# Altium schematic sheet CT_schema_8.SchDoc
size 274 x 160 mm
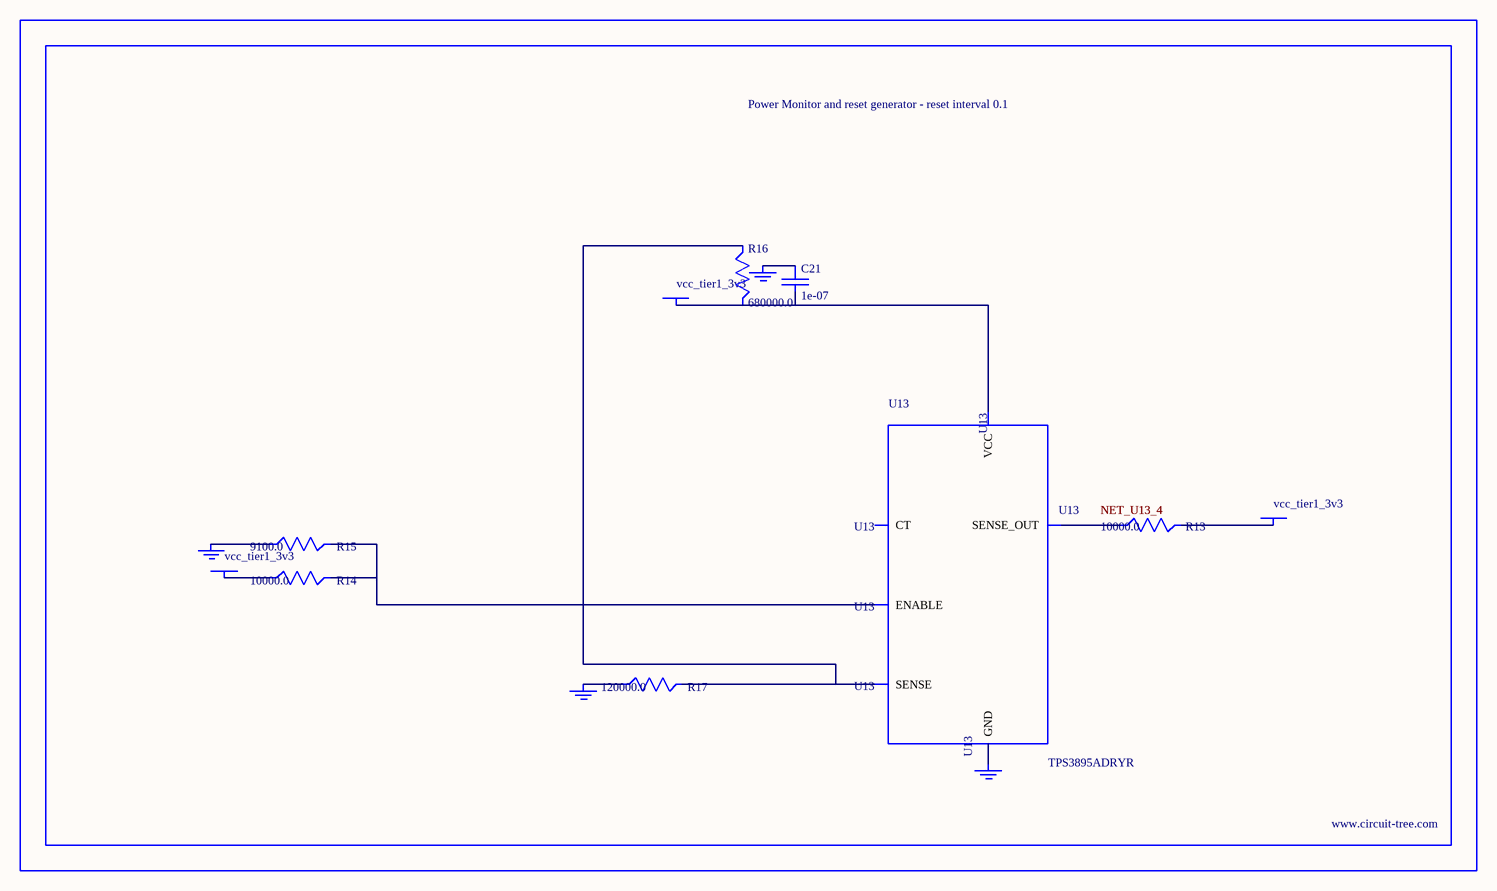
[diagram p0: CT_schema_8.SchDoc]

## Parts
BORDER7  (no value)
C21  1e-07  [C0402]
GND_INSTANCE_7_0  (no value)
GND_INSTANCE_7_1  (no value)
GND_INSTANCE_7_2  (no value)
GND_INSTANCE_7_3  (no value)
POWER_INSTANCE_7_0  vcc_tier1_3v3
POWER_INSTANCE_7_1  vcc_tier1_3v3
POWER_INSTANCE_7_2  vcc_tier1_3v3
R13  10000.0  [R0603]
R14  10000.0  [R0603]
R15  9100.0  [R0603]
R16  680000.0  [R0603]
R17  120000.0  [R0603]
U13  TPS3895ADRYR  [SON-6]

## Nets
NetC21_1: C21.1 GND_INSTANCE_7_2.0(GND)
NetC21_2: C21.2 POWER_INSTANCE_7_2.0(PWR) R16.2 U13.6(VCC)
NetGND_INSTANCE_7_0_0: GND_INSTANCE_7_0.0(GND) R15.1
NetGND_INSTANCE_7_1_0: GND_INSTANCE_7_1.0(GND) R17.1
NetGND_INSTANCE_7_3_0: GND_INSTANCE_7_3.0(GND) U13.2(GND)
NetPOWER_INSTANCE_7_0_0: POWER_INSTANCE_7_0.0(PWR) R14.1
NetPOWER_INSTANCE_7_1_0: POWER_INSTANCE_7_1.0(PWR) R13.2
NetR13_1: R13.1 U13.4(SENSE_OUT)
NetR14_2: R14.2 R15.2 U13.1(ENABLE)
NetR16_1: R16.1 R17.2 U13.3(SENSE)

Not connected (* = marked no-connect by the designer): U13 5(CT)

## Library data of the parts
BORDER7 = BORDER_PAGE7
C21 = C0402C104K3RACTU
GND_INSTANCE_7_0-GND_INSTANCE_7_3 = GND
POWER_INSTANCE_7_0-POWER_INSTANCE_7_2 = PWR
R13 R14 = RC0603JR-0710KL
R15 = RC0603JR-079K1L
R16 = RC0603JR-07680KL
R17 = RC0603JR-07120KL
